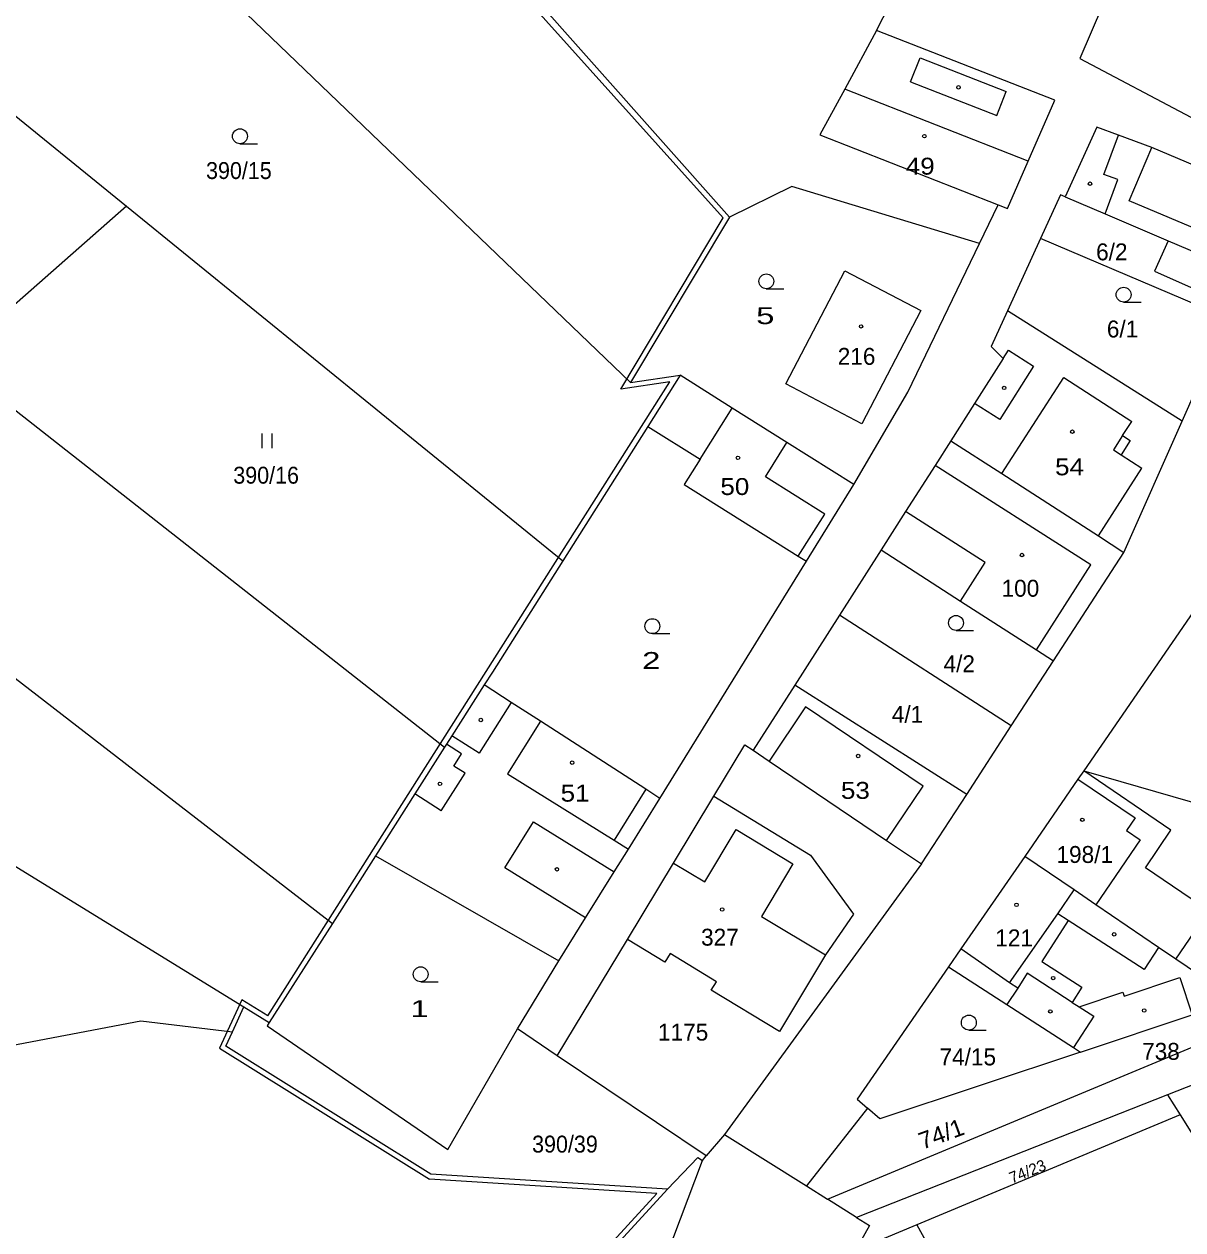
# Model space of a CAD drawing. Extents: x -758887 to -754328, y -1031688 to -1029144.
# Drawn here: x -756631.8 to -756515.3, y -1030649.6 to -1030528.5 of the extents above; entities that cross this region are included whole.
import ezdxf
from ezdxf.enums import TextEntityAlignment as Align

# ---------------------------------------------------------------- set-up
doc = ezdxf.new("R2010")
doc.units = 0
doc.header["$LTSCALE"] = 0.68
for name, color, linetype, lineweight in [('1', 7, 'Continuous', 25), ('3', 7, 'Continuous', 25), ('4', 7, 'Continuous', 13), ('5', 7, 'Continuous', 25)]:
    doc.layers.add(name, color=color, linetype=linetype, lineweight=lineweight)
doc.layers.add('2', color=7, linetype='Continuous')

msp = doc.modelspace()

# ---------------------------------------------------------------- linework, layer by layer
at = {"layer": '1'}
for p, q in [((-756639, -1030499.08), (-756570.87, -1030564.48)), ((-756699.33, -1030542.79), (-756600.85, -1030618.83)), ((-756621.54, -1030546.75), (-756639.13, -1030562.23)), ((-756535.8, -1030550.52), (-756533.91, -1030546.62)), ((-756529.65, -1030550), (-756532.98, -1030557.27)), ((-756639.13, -1030562.23), (-756589.57, -1030601.12)), ((-756570.87, -1030564.48), (-756565.9, -1030563.74)), ((-756569.15, -1030568.88), (-756577.68, -1030582.38)), ((-756545.68, -1030581.29), (-756549.88, -1030587.86)), ((-756528.35, -1030592.43), (-756521.28, -1030581.54)), ((-756567.92, -1030606.27), (-756553.19, -1030582.43)), ((-756549.88, -1030587.86), (-756554.37, -1030594.89)), ((-756532.6, -1030598.97), (-756528.35, -1030592.43)), ((-756554.37, -1030594.89), (-756558.55, -1030601.43)), ((-756525.31, -1030603.49), (-756505.53, -1030609.22)), ((-756541.62, -1030612.85), (-756561.42, -1030640.03)), ((-756578.24, -1030632.12), (-756571.19, -1030620.45)), ((-756510.42, -1030626.25), (-756516.05, -1030622.42)), ((-756610.9, -1030629.71), (-756609.74, -1030627.21)), ((-756578.24, -1030632.12), (-756582.23, -1030629.43)), ((-756563.27, -1030642.19), (-756578.24, -1030632.12)), ((-756516.89, -1030636.06), (-756548.16, -1030648.36)), ((-756515.63, -1030638.06), (-756542.09, -1030649.11)), ((-756561.42, -1030640.03), (-756563.27, -1030642.19)), ((-756561.42, -1030640.03), (-756553.18, -1030645.21)), ((-756570.62, -1030661.18), (-756563.65, -1030642.64)), ((-756548.16, -1030648.36), (-756551.08, -1030646.53)), ((-756542.09, -1030649.11), (-756548.27, -1030651.69)), ((-756542.09, -1030649.11), (-756531.73, -1030667.81))]:
    msp.add_line(p, q, dxfattribs=at)
for points in [[(-756565.46, -1030494.05), (-756595.07, -1030509.4), (-756560.94, -1030547.86)], [(-756489.22, -1030526.88), (-756483.33, -1030518.31), (-756494.29, -1030510.42), (-756497.43, -1030507.94), (-756508.95, -1030497.19), (-756510.09, -1030496.54), (-756510.6, -1030496.77), (-756525.69, -1030531.93), (-756514.55, -1030537.82), (-756511.73, -1030539.11)], [(-756546.14, -1030529.11), (-756543.49, -1030523.93), (-756540.01, -1030501.62)], [(-756657.97, -1030517.15), (-756621.54, -1030546.75), (-756577.68, -1030582.38)], [(-756546.14, -1030529.11), (-756549.34, -1030535), (-756551.84, -1030539.6), (-756533.91, -1030546.62)], [(-756533.91, -1030546.62), (-756532.99, -1030546.98), (-756530.91, -1030542.22), (-756528.22, -1030536.09), (-756546.14, -1030529.11)], [(-756510.29, -1030556.81), (-756508.87, -1030553.61), (-756507.98, -1030551.62), (-756505.62, -1030546.3), (-756518.46, -1030540.86), (-756521.83, -1030539.62), (-756523.99, -1030538.82), (-756527.18, -1030545.83)], [(-756535.8, -1030550.52), (-756554.66, -1030544.78), (-756560.94, -1030547.86), (-756570.87, -1030564.48)], [(-756527.18, -1030545.83), (-756527.64, -1030545.63), (-756529.65, -1030550)], [(-756527.18, -1030545.83), (-756523.16, -1030547.54), (-756516.83, -1030550.23), (-756518.19, -1030553.3), (-756510.29, -1030556.81)], [(-756548.44, -1030574.74), (-756543, -1030565.45), (-756535.8, -1030550.52)], [(-756515.42, -1030568.35), (-756510.82, -1030558), (-756529.65, -1030550)], [(-756312.59, -1030555.25), (-756315.52, -1030551.79), (-756381.49, -1030591.35), (-756401.18, -1030595.86), (-756437.11, -1030607.98), (-756464.98, -1030615.64), (-756516.89, -1030636.06), (-756515.63, -1030638.06), (-756495.42, -1030670.29), (-756493.95, -1030672.9)], [(-756724.6, -1030556.59), (-756609.74, -1030627.21), (-756607.19, -1030628.79)], [(-756532.98, -1030557.27), (-756534.63, -1030560.87), (-756533.42, -1030562.06), (-756536.29, -1030566.57), (-756538.68, -1030570.33)], [(-756521.28, -1030581.54), (-756515.42, -1030568.35), (-756532.98, -1030557.27)], [(-756565.9, -1030563.74), (-756569.15, -1030568.88), (-756563.89, -1030572.19)], [(-756548.44, -1030574.74), (-756555.15, -1030570.51), (-756560.66, -1030567.05), (-756565.9, -1030563.74)], [(-756538.68, -1030570.33), (-756540.25, -1030572.8), (-756543.23, -1030577.45), (-756545.68, -1030581.29)], [(-756538.68, -1030570.33), (-756533.56, -1030573.63), (-756523.84, -1030579.89), (-756521.28, -1030581.54)], [(-756563.89, -1030572.19), (-756565.47, -1030574.71), (-756554.01, -1030581.93), (-756553.19, -1030582.43), (-756548.44, -1030574.74)], [(-756545.68, -1030581.29), (-756537.69, -1030586.43), (-756530.05, -1030591.34), (-756528.35, -1030592.43)], [(-756577.68, -1030582.38), (-756584.76, -1030593.58), (-756585.59, -1030594.87)], [(-756494.34, -1030586.61), (-756511.08, -1030582.87), (-756525.31, -1030603.49)], [(-756537.08, -1030605.86), (-756532.6, -1030598.97), (-756549.88, -1030587.86)], [(-756585.59, -1030594.87), (-756588.84, -1030599.97), (-756589.38, -1030600.82), (-756589.57, -1030601.12)], [(-756567.92, -1030606.27), (-756569.35, -1030605.35), (-756579.94, -1030598.52), (-756582.86, -1030596.63), (-756585.59, -1030594.87)], [(-756541.62, -1030612.85), (-756537.08, -1030605.86), (-756554.37, -1030594.89)], [(-756589.57, -1030601.12), (-756592.55, -1030605.79), (-756596.52, -1030612.03), (-756578.09, -1030622.6)], [(-756562.51, -1030606.05), (-756559.38, -1030600.87), (-756558.55, -1030601.43)], [(-756558.55, -1030601.43), (-756556.95, -1030602.51), (-756545.13, -1030610.48), (-756541.62, -1030612.85)], [(-756525.31, -1030603.49), (-756525.89, -1030604.33), (-756531.24, -1030612.09)], [(-756516.05, -1030622.42), (-756512.74, -1030617.55), (-756519.11, -1030613.23), (-756516.54, -1030609.45), (-756525.31, -1030603.49)], [(-756578.09, -1030622.6), (-756575.4, -1030618.28), (-756572.52, -1030613.65), (-756571.09, -1030611.36), (-756567.92, -1030606.27)], [(-756571.19, -1030620.45), (-756566.55, -1030612.76), (-756562.51, -1030606.05)], [(-756562.51, -1030606.05), (-756552.78, -1030611.96), (-756548.45, -1030617.91), (-756551.28, -1030621.99), (-756555.91, -1030629.7), (-756562.76, -1030625.53), (-756562.24, -1030624.68), (-756566.9, -1030621.85), (-756567.43, -1030622.73), (-756571.19, -1030620.45)], [(-756596.52, -1030612.03), (-756600.85, -1030618.83), (-756607.19, -1030628.79)], [(-756531.24, -1030612.09), (-756537.66, -1030621.39), (-756538.91, -1030623.2)], [(-756516.05, -1030622.42), (-756517.8, -1030621.23), (-756524.09, -1030616.95), (-756526.28, -1030615.46), (-756531.24, -1030612.09)], [(-756525.65, -1030631.75), (-756545.81, -1030638.46), (-756547.04, -1030637.4), (-756553.18, -1030645.21), (-756551.08, -1030646.53), (-756475.34, -1030614.99)], [(-756607.19, -1030628.79), (-756607.4, -1030629.12), (-756589.24, -1030641.54), (-756582.23, -1030629.43), (-756578.09, -1030622.6)], [(-756538.91, -1030623.2), (-756548.08, -1030636.5), (-756547.04, -1030637.4)], [(-756538.91, -1030623.2), (-756533.03, -1030626.99), (-756526.34, -1030631.3), (-756525.65, -1030631.75)], [(-756525.65, -1030631.75), (-756514.41, -1030628), (-756513.91, -1030627.83)], [(-756642.87, -1030632.93), (-756620.11, -1030628.61), (-756610.9, -1030629.71)], [(-756567.17, -1030645.53), (-756590.94, -1030644.02), (-756611.57, -1030631.16), (-756610.9, -1030629.71)], [(-756567.17, -1030645.53), (-756564.11, -1030642.33), (-756563.65, -1030642.64), (-756563.27, -1030642.19)], [(-756622.25, -1030695.77), (-756617.82, -1030689.9), (-756596.84, -1030677.93), (-756567.17, -1030645.53)], [(-756548.16, -1030648.36), (-756546.86, -1030649.18), (-756548.27, -1030651.69)]]:
    msp.add_lwpolyline(points, dxfattribs=at)
msp.add_lwpolyline([(-756555.26, -1030564.62), (-756549.33, -1030553.26), (-756541.7, -1030557.24), (-756547.63, -1030568.63)], close=True, dxfattribs=at)
at = {"layer": '3'}
for p, q in [((-756610.143, -1030540.48), (-756608.393, -1030540.48)), ((-756557.223, -1030555.06), (-756555.473, -1030555.06)), ((-756521.303, -1030556.4), (-756519.553, -1030556.4)), ((-756607.921, -1030571.09), (-756607.921, -1030569.59)), ((-756606.92, -1030571.09), (-756606.92, -1030569.59)), ((-756538.153, -1030589.38), (-756536.403, -1030589.38)), ((-756568.683, -1030589.71), (-756566.933, -1030589.71)), ((-756591.973, -1030624.69), (-756590.223, -1030624.69)), ((-756536.863, -1030629.54), (-756535.113, -1030629.54))]:
    msp.add_line(p, q, dxfattribs=at)
for centre in [(-756610.1429, -1030539.7298), (-756557.2229, -1030554.3098), (-756521.3029, -1030555.6498), (-756568.6829, -1030588.9598), (-756538.1529, -1030588.6298), (-756591.9729, -1030623.9398), (-756536.8629, -1030628.7898)]:
    msp.add_circle(centre, 0.75, dxfattribs=at)
at = {"layer": '4'}
for p, q in [((-756561.56, -1030547.92), (-756619.73, -1030483.2)), ((-756542.72, -1030534.26), (-756541.77, -1030531.84)), ((-756541.77, -1030531.84), (-756533.11, -1030535.23)), ((-756530.91, -1030542.22), (-756549.34, -1030535)), ((-756542.72, -1030534.26), (-756534.06, -1030537.66)), ((-756534.06, -1030537.66), (-756533.11, -1030535.23)), ((-756523.29, -1030543.56), (-756521.83, -1030539.62)), ((-756520.73, -1030546.22), (-756518.46, -1030540.86)), ((-756521.88, -1030544.07), (-756523.29, -1030543.56)), ((-756523.16, -1030547.54), (-756521.88, -1030544.07)), ((-756507.98, -1030551.62), (-756520.73, -1030546.22)), ((-756571.84, -1030565.13), (-756561.56, -1030547.92)), ((-756516.83, -1030550.23), (-756508.87, -1030553.61)), ((-756533.42, -1030562.06), (-756532.89, -1030561.21)), ((-756532.89, -1030561.21), (-756530.35, -1030562.82)), ((-756530.35, -1030562.82), (-756533.76, -1030568.18)), ((-756533.56, -1030573.63), (-756527.33, -1030563.96)), ((-756527.33, -1030563.96), (-756520.48, -1030568.38)), ((-756533.76, -1030568.18), (-756536.29, -1030566.57)), ((-756563.89, -1030572.19), (-756560.66, -1030567.05)), ((-756521.4, -1030569.81), (-756520.48, -1030568.38)), ((-756521.4, -1030569.81), (-756522.33, -1030571.24)), ((-756521.4, -1030569.81), (-756520.64, -1030570.31)), ((-756557.32, -1030573.95), (-756555.15, -1030570.51)), ((-756522.33, -1030571.24), (-756521.56, -1030571.74)), ((-756520.64, -1030570.31), (-756521.56, -1030571.74)), ((-756521.56, -1030571.74), (-756519.46, -1030573.09)), ((-756524.6, -1030582.8), (-756540.25, -1030572.8)), ((-756523.84, -1030579.89), (-756519.46, -1030573.09)), ((-756535.22, -1030582.57), (-756543.23, -1030577.45)), ((-756537.69, -1030586.43), (-756535.22, -1030582.57)), ((-756530.05, -1030591.34), (-756524.6, -1030582.8)), ((-756582.86, -1030596.63), (-756586.1, -1030601.72)), ((-756553.28, -1030597.07), (-756556.95, -1030602.51)), ((-756579.94, -1030598.52), (-756583.23, -1030603.8)), ((-756586.1, -1030601.72), (-756588.84, -1030599.97)), ((-756587.86, -1030601.78), (-756589.38, -1030600.82)), ((-756588.64, -1030603.01), (-756587.86, -1030601.78)), ((-756589.91, -1030607.53), (-756587.5, -1030603.73)), ((-756587.5, -1030603.73), (-756588.64, -1030603.01)), ((-756583.23, -1030603.8), (-756572.53, -1030610.46)), ((-756569.35, -1030605.35), (-756572.53, -1030610.46)), ((-756525.89, -1030604.33), (-756520.15, -1030608.23)), ((-756589.91, -1030607.53), (-756592.55, -1030605.79)), ((-756583.51, -1030613.23), (-756580.63, -1030608.61)), ((-756580.63, -1030608.61), (-756572.52, -1030613.65)), ((-756520.15, -1030608.23), (-756521.01, -1030609.49)), ((-756563.42, -1030614.65), (-756560.26, -1030609.39)), ((-756560.26, -1030609.39), (-756554.55, -1030612.84)), ((-756572.53, -1030610.46), (-756571.09, -1030611.36)), ((-756575.4, -1030618.28), (-756583.51, -1030613.23)), ((-756566.55, -1030612.76), (-756563.42, -1030614.65)), ((-756554.55, -1030612.84), (-756557.7, -1030618.12)), ((-756527.93, -1030617.85), (-756526.28, -1030615.46)), ((-756557.7, -1030618.12), (-756551.28, -1030621.99)), ((-756526.88, -1030618.52), (-756529.53, -1030622.64)), ((-756526.88, -1030618.52), (-756527.93, -1030617.85)), ((-756519.23, -1030623.45), (-756526.88, -1030618.52)), ((-756532.79, -1030624.79), (-756537.66, -1030621.39)), ((-756517.8, -1030621.23), (-756519.23, -1030623.45)), ((-756529.53, -1030622.64), (-756525.5, -1030625.24)), ((-756530.99, -1030623.84), (-756531.95, -1030625.33)), ((-756526.47, -1030626.76), (-756530.99, -1030623.84)), ((-756521.26, -1030626.12), (-756515.66, -1030624.25)), ((-756515.66, -1030624.25), (-756514.41, -1030628)), ((-756531.95, -1030625.33), (-756533.03, -1030626.99)), ((-756525.5, -1030625.24), (-756526.47, -1030626.76)), ((-756525.77, -1030627.21), (-756521.38, -1030625.74)), ((-756521.38, -1030625.74), (-756521.26, -1030626.12)), ((-756526.47, -1030626.76), (-756525.77, -1030627.21)), ((-756524.31, -1030628.15), (-756526.34, -1030631.3)), ((-756525.77, -1030627.21), (-756524.31, -1030628.15)), ((-756568.24, -1030645.96), (-756591.1, -1030644.51)), ((-756597.16, -1030677.54), (-756568.24, -1030645.96))]:
    msp.add_line(p, q, dxfattribs=at)
for points in [[(-756607.35, -1030628.1), (-756566.91, -1030564.4), (-756571.84, -1030565.13)], [(-756554.01, -1030581.93), (-756551.35, -1030577.71), (-756557.32, -1030573.95)], [(-756545.13, -1030610.48), (-756541.46, -1030605.04), (-756553.28, -1030597.07)], [(-756521.01, -1030609.49), (-756519.64, -1030610.42), (-756524.09, -1030616.95)], [(-756531.95, -1030625.33), (-756532.79, -1030624.79), (-756527.93, -1030617.85)], [(-756607.35, -1030628.1), (-756609.96, -1030626.49), (-756612.21, -1030631.35), (-756591.1, -1030644.51)]]:
    msp.add_lwpolyline(points, dxfattribs=at)
at = {"layer": '5'}
for centre in [(-756537.8968, -1030534.8192), (-756541.3368, -1030539.7292), (-756524.6868, -1030544.4992), (-756547.6968, -1030558.8392), (-756533.3168, -1030565.0192), (-756526.4568, -1030569.4192), (-756560.0768, -1030572.0492), (-756531.5168, -1030581.8092), (-756585.9268, -1030598.3892), (-756576.7468, -1030602.6792), (-756547.9868, -1030601.9992), (-756590.0368, -1030604.7992), (-756525.4568, -1030608.4092), (-756578.2768, -1030613.3892), (-756561.6668, -1030617.4292), (-756532.0768, -1030616.9592), (-756522.2568, -1030619.9292), (-756528.3868, -1030624.3192), (-756528.6768, -1030627.6692), (-756519.2368, -1030627.5792)]:
    msp.add_circle(centre, 0.175, dxfattribs=at)

# ---------------------------------------------------------------- texts
at = {"layer": '2'}
for s, width, p in [('390/15', 0.95, (-756610.249, -1030544.03)), ('49', 1.15, (-756541.75, -1030543.59)), ('5', 1.45, (-756557.33, -1030558.61)), ('54', 1.15, (-756526.74, -1030573.8)), ('390/16', 0.95, (-756607.509, -1030574.64)), ('50', 1.15, (-756560.39, -1030575.78)), ('2', 1.45, (-756568.79, -1030593.26)), ('51', 1.15, (-756576.45, -1030606.59)), ('53', 1.15, (-756548.27, -1030606.31)), ('1', 1.45, (-756592.08, -1030628.24)), ('390/39', 0.95, (-756577.469, -1030641.85))]:
    msp.add_text(s, height=1.7, dxfattribs=dict(at, width=width)).set_placement(p, align=Align.CENTER)
for s, p in [('6/2', (-756522.489, -1030552.2)), ('6/1', (-756521.409, -1030559.95)), ('216', (-756548.149, -1030562.7)), ('100', (-756531.679, -1030586)), ('4/2', (-756537.829, -1030593.59)), ('4/1', (-756543.029, -1030598.67)), ('198/1', (-756525.21, -1030612.75)), ('327', (-756561.889, -1030621.06)), ('121', (-756532.309, -1030621.13)), ('1175', (-756565.59, -1030630.6)), ('738', (-756517.549, -1030632.53)), ('74/15', (-756536.97, -1030633.09))]:
    msp.add_text(s, height=1.7, dxfattribs=at).set_placement(p, align=Align.CENTER)
at = {"layer": '2', "width": 1.05}
msp.add_text('74/1', height=1.7, rotation=20, dxfattribs=at).set_placement((-756539.3452, -1030640.7779), align=Align.CENTER)
at = {"layer": '2'}
msp.add_text('74/23', height=1.14, rotation=22, dxfattribs=at).set_placement((-756530.753, -1030644.2707), align=Align.CENTER)

doc.saveas('drawing.dxf')
